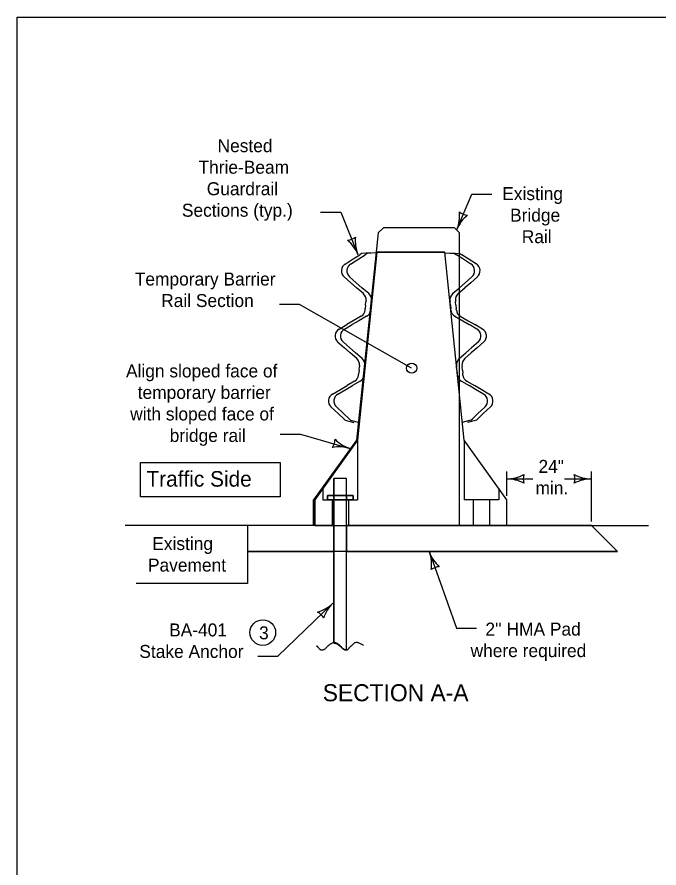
# Model space of a CAD drawing. Extents: x 10028 to 81668, y 3581 to 11018.
# Drawn here: x 13733 to 14485, y 8948 to 9944 of the extents above; entities that cross this region are included whole.
import ezdxf

# ---------------------------------------------------------------- set-up
doc = ezdxf.new("R2010")
doc.units = 0
for name, color, linetype in [('dsnCellsNorthArrow', 7, 'Continuous'), ('dsnTextTabulation', 7, 'Continuous'), ('Level 41', 7, 'Continuous'), ('Level 9', 7, 'Continuous'), ('SheetBorder', 7, 'Continuous')]:
    doc.layers.add(name, color=color, linetype=linetype)

msp = doc.modelspace()

# ---------------------------------------------------------------- linework, layer by layer
at = {"layer": 'dsnCellsNorthArrow'}
for p, q in [((14162.04, 9697.14), (14155.56, 9691.46)), ((14245.18, 9697.14), (14162.04, 9697.14)), ((14250.93, 9691.16), (14245.18, 9697.14)), ((14155.56, 9691.46), (14130.32, 9448.52)), ((14250.93, 9502.48), (14250.93, 9691.16)), ((14250.93, 9348.52), (14250.93, 9502.48)), ((14130.32, 9448.52), (14079.75, 9378.52)), ((14079.75, 9348.52), (14079.75, 9378.52))]:
    msp.add_line(p, q, dxfattribs=at)
at = {"layer": 'dsnTextTabulation'}
for p, q in [((14248.01, 9695.32), (14265.38, 9736.6)), ((14265.38, 9736.6), (14288.98, 9736.6)), ((14088.2, 9715.55), (14111.8, 9715.55)), ((14111.8, 9715.55), (14132.03, 9665.97)), ((14131.45, 9448.52), (14153.95, 9668.52)), ((14136.25, 9666.95), (14134.02, 9665.54)), ((14146.96, 9667.77), (14136.25, 9666.95)), ((14142.65, 9666.95), (14140.42, 9665.54)), ((14153.36, 9667.77), (14142.65, 9666.95)), ((14153.95, 9668.52), (14233.95, 9668.52)), ((14256.45, 9448.52), (14233.95, 9668.52)), ((14234.35, 9667.77), (14245.05, 9666.95)), ((14240.74, 9667.77), (14251.45, 9666.95)), ((14245.05, 9666.95), (14247.29, 9665.54)), ((14251.45, 9666.95), (14253.68, 9665.54)), ((14116.98, 9654.79), (14126.48, 9660.78)), ((14123.38, 9654.79), (14132.87, 9660.78)), ((14126.48, 9660.78), (14134.02, 9665.54)), ((14132.88, 9660.78), (14140.42, 9665.54)), ((14254.83, 9660.78), (14247.29, 9665.54)), ((14261.23, 9660.78), (14253.68, 9665.54)), ((14264.32, 9654.79), (14254.83, 9660.78)), ((14270.72, 9654.79), (14261.23, 9660.78)), ((14115.82, 9639.74), (14123.62, 9632.93)), ((14122.22, 9639.74), (14130.02, 9632.93)), ((14265.49, 9639.74), (14257.69, 9632.93)), ((14271.88, 9639.74), (14264.08, 9632.93)), ((14123.62, 9632.93), (14130.33, 9627.08)), ((14130.02, 9632.93), (14136.73, 9627.08)), ((14138.34, 9620.09), (14130.33, 9627.08)), ((14144.74, 9620.09), (14136.73, 9627.08)), ((14242.96, 9620.09), (14250.97, 9627.08)), ((14249.36, 9620.09), (14257.37, 9627.08)), ((14257.69, 9632.93), (14250.97, 9627.08)), ((14264.08, 9632.93), (14257.37, 9627.08)), ((14063.62, 9607.48), (14040.02, 9607.48)), ((14194.92, 9532.77), (14063.62, 9607.48)), ((14141, 9606.59), (14140.63, 9602.86)), ((14140.98, 9606.45), (14141.36, 9610.33)), ((14141.53, 9612.08), (14141.36, 9610.33)), ((14147.39, 9606.59), (14147.03, 9602.86)), ((14147.38, 9606.45), (14147.76, 9610.33)), ((14147.93, 9612.08), (14147.76, 9610.33)), ((14239.77, 9612.08), (14239.95, 9610.33)), ((14240.32, 9606.45), (14239.95, 9610.33)), ((14240.31, 9606.59), (14240.67, 9602.86)), ((14246.17, 9612.08), (14246.34, 9610.33)), ((14246.72, 9606.45), (14246.34, 9610.33)), ((14246.71, 9606.59), (14247.07, 9602.86)), ((14140.44, 9600.82), (14140.63, 9602.86)), ((14146.83, 9600.82), (14147.03, 9602.86)), ((14240.87, 9600.82), (14240.67, 9602.86)), ((14247.27, 9600.82), (14247.07, 9602.86)), ((14126.57, 9588.28), (14118.85, 9583.83)), ((14132.97, 9588.28), (14125.25, 9583.83)), ((14135.76, 9593.58), (14126.57, 9588.28)), ((14142.16, 9593.58), (14132.97, 9588.28)), ((14245.55, 9593.58), (14254.73, 9588.28)), ((14251.94, 9593.58), (14261.13, 9588.28)), ((14254.73, 9588.28), (14262.45, 9583.83)), ((14261.13, 9588.28), (14268.85, 9583.83)), ((14109.87, 9578.65), (14118.85, 9583.83)), ((14116.26, 9578.65), (14125.25, 9583.83)), ((14271.44, 9578.65), (14262.45, 9583.83)), ((14277.84, 9578.65), (14268.85, 9583.83)), ((14108.12, 9563.63), (14116.2, 9556.59)), ((14114.52, 9563.63), (14122.6, 9556.59)), ((14116.2, 9556.59), (14122.91, 9550.73)), ((14122.6, 9556.59), (14129.31, 9550.73)), ((14265.11, 9556.59), (14258.39, 9550.73)), ((14271.51, 9556.59), (14264.79, 9550.73)), ((14273.18, 9563.63), (14265.11, 9556.59)), ((14279.58, 9563.63), (14271.51, 9556.59)), ((14130.65, 9543.98), (14122.91, 9550.73)), ((14137.04, 9543.98), (14129.31, 9550.73)), ((14250.66, 9543.98), (14258.39, 9550.73)), ((14257.06, 9543.98), (14264.79, 9550.73)), ((14132.74, 9524.71), (14132.96, 9526.93)), ((14133.32, 9530.66), (14132.96, 9526.93)), ((14133.32, 9530.66), (14133.68, 9534.4)), ((14133.84, 9535.98), (14133.68, 9534.4)), ((14139.14, 9524.71), (14139.35, 9526.93)), ((14139.72, 9530.66), (14139.35, 9526.93)), ((14139.72, 9530.66), (14140.08, 9534.4)), ((14140.23, 9535.98), (14140.08, 9534.4)), ((14247.47, 9535.98), (14247.62, 9534.4)), ((14247.99, 9530.66), (14247.62, 9534.4)), ((14247.99, 9530.66), (14248.35, 9526.93)), ((14248.57, 9524.71), (14248.35, 9526.93)), ((14253.87, 9535.98), (14254.02, 9534.4)), ((14254.38, 9530.66), (14254.02, 9534.4)), ((14254.38, 9530.66), (14254.75, 9526.93)), ((14254.96, 9524.71), (14254.75, 9526.93)), ((14128.06, 9517.47), (14119.17, 9512.35)), ((14134.46, 9517.47), (14125.57, 9512.35)), ((14253.24, 9517.47), (14262.14, 9512.35)), ((14259.64, 9517.47), (14268.54, 9512.35)), ((14102.17, 9502.55), (14111.45, 9507.9)), ((14108.57, 9502.55), (14117.85, 9507.9)), ((14111.45, 9507.9), (14119.17, 9512.35)), ((14117.85, 9507.9), (14125.57, 9512.35)), ((14269.86, 9507.9), (14262.14, 9512.35)), ((14276.25, 9507.9), (14268.54, 9512.35)), ((14279.14, 9502.55), (14269.86, 9507.9)), ((14285.54, 9502.55), (14276.25, 9507.9)), ((14100.4, 9487.55), (14108.81, 9479.61)), ((14106.8, 9487.55), (14115.2, 9479.61)), ((14280.91, 9487.55), (14272.5, 9479.61)), ((14287.3, 9487.55), (14278.9, 9479.61)), ((14108.81, 9479.61), (14115.29, 9473.48)), ((14115.2, 9479.61), (14121.69, 9473.48)), ((14272.5, 9479.61), (14266.02, 9473.48)), ((14278.9, 9479.61), (14272.42, 9473.48)), ((14116.96, 9471.9), (14115.29, 9473.48)), ((14116.96, 9471.9), (14127.31, 9469.03)), ((14123.36, 9471.9), (14121.69, 9473.48)), ((14123.36, 9471.9), (14133.71, 9469.03)), ((14264.35, 9471.9), (14254, 9469.03)), ((14270.74, 9471.9), (14260.39, 9469.03)), ((14264.35, 9471.9), (14266.02, 9473.48)), ((14270.74, 9471.9), (14272.42, 9473.48)), ((14040.93, 9455.58), (14064.54, 9455.58)), ((14064.54, 9455.58), (14122.64, 9438.73)), ((14081.45, 9378.52), (14131.45, 9448.52)), ((14306.45, 9378.52), (14256.45, 9448.52)), ((14306.45, 9383.51), (14306.45, 9411.87)), ((14405.49, 9353.28), (14405.49, 9411.87)), ((14306.45, 9403.11), (14336.86, 9403.11)), ((14374.18, 9403.11), (14405.49, 9403.11)), ((14081.45, 9348.52), (14081.45, 9378.52)), ((14306.45, 9348.52), (14306.45, 9378.52)), ((14081.45, 9348.52), (14306.45, 9348.52)), ((14215.75, 9317.4), (14247.38, 9228.36)), ((14038.11, 9195.72), (14102.52, 9257.52)), ((14247.38, 9228.36), (14270.98, 9228.36)), ((14014.5, 9195.72), (14038.11, 9195.72))]:
    msp.add_line(p, q, dxfattribs=at)
msp.add_circle((14020.5, 9223.19), 15, dxfattribs=at)
for centre, radius, start, end in [((14208.65, 9711.35), 42.5, 337.83753, 5.91002), ((14287.37, 9679.28), 42.5, 129.76504, 157.83753), ((14261.46, 9728.32), 16.42, 230.10418, 265.57088), ((14118.57, 9698.97), 16.42, 274.46679, 309.93349), ((14171.38, 9682.03), 42.5, 174.12765, 202.20014), ((14092.68, 9649.92), 42.5, 22.20014, 50.27263), ((14088.71, 9449.63), 16.42, 324.45544, 359.92214), ((14135.64, 9479.19), 42.5, 224.1163, 252.18879), ((14109.64, 9398.27), 42.5, 72.18879, 100.26128), ((14306.45, 9445.61), 42.5, 270, 298.07249), ((14342.09, 9403.11), 16.42, 162.26665, 197.73335), ((14369.85, 9403.11), 16.42, 342.26665, 17.73335), ((14405.49, 9445.61), 42.5, 241.92751, 270), ((14306.45, 9360.61), 42.5, 61.92751, 90), ((14405.49, 9360.61), 42.5, 90, 118.07249), ((14255.63, 9332.08), 42.5, 200.20763, 228.28012), ((14175.86, 9302.72), 42.5, 352.13514, 20.20763), ((14228.05, 9283.96), 16.42, 92.47427, 127.94098), ((14073.1, 9288.19), 42.5, 285.73709, 313.80957), ((14131.95, 9226.85), 42.5, 133.80957, 161.88206), ((14076.81, 9232.85), 16.42, 26.07622, 61.54292)]:
    msp.add_arc(centre, radius, start, end, dxfattribs=at)
for centre, major_axis, start_param, end_param in [((14122.06, 9646.83), (9.43, -0.92), 2.229659, 4.096128), ((14128.46, 9646.83), (9.43, -0.92), 2.229659, 4.096128), ((14259.24, 9646.83), (-9.43, -0.92), 2.187057, 4.053527), ((14265.64, 9646.83), (-9.43, -0.92), 2.187057, 4.053527), ((14132.1, 9613), (9.43, -0.92), 0, 0.954538), ((14138.5, 9613), (9.43, -0.92), 0, 0.954538), ((14249.21, 9613), (-9.43, -0.92), 5.328647, 6.283185), ((14255.6, 9613), (-9.43, -0.92), 5.328647, 6.283185), ((14131, 9601.74), (-9.43, 0.92), 2.187055, 3.141593), ((14137.4, 9601.74), (-9.43, 0.92), 2.187055, 3.141593), ((14250.31, 9601.74), (9.43, 0.92), 3.141593, 4.096131), ((14256.7, 9601.74), (9.43, 0.92), 3.141593, 4.096131), ((14114.62, 9570.49), (-9.43, 0.92), 5.32865, 7.195119), ((14121.02, 9570.49), (-9.43, 0.92), 5.32865, 7.195119), ((14266.68, 9570.49), (9.43, 0.92), 5.371251, 7.237721), ((14273.08, 9570.49), (9.43, 0.92), 5.371251, 7.237721), ((14124.4, 9536.9), (9.43, -0.92), 0, 0.954538), ((14130.8, 9536.9), (9.43, -0.92), 0, 0.954538), ((14256.9, 9536.9), (-9.43, -0.92), 5.328647, 6.283185), ((14263.3, 9536.9), (-9.43, -0.92), 5.328647, 6.283185), ((14123.31, 9525.63), (-9.43, 0.92), 2.187055, 3.141593), ((14129.7, 9525.63), (-9.43, 0.92), 2.187055, 3.141593), ((14258, 9525.63), (9.43, 0.92), 3.141593, 4.096131), ((14264.4, 9525.63), (9.43, 0.92), 3.141593, 4.096131), ((14106.93, 9494.38), (-9.43, 0.92), 5.32865, 7.195119), ((14113.32, 9494.38), (-9.43, 0.92), 5.32865, 7.195119), ((14274.38, 9494.38), (9.43, 0.92), 5.371251, 7.237721), ((14280.78, 9494.38), (9.43, 0.92), 5.371251, 7.237721)]:
    msp.add_ellipse(centre, major_axis=major_axis, ratio=0.994906, start_param=start_param, end_param=end_param, dxfattribs=at)
at = {"layer": 'Level 41'}
for p, q in [((14131.45, 9448.52), (14131.45, 9378.52)), ((14256.45, 9448.52), (14256.45, 9378.52)), ((14090.98, 9391.86), (14090.98, 9378.52)), ((14296.92, 9391.86), (14296.92, 9378.52)), ((14090.98, 9378.52), (14131.45, 9378.52)), ((14101.62, 9378.52), (14101.62, 9348.52)), ((14120.82, 9378.52), (14120.82, 9348.52)), ((14296.92, 9378.52), (14256.45, 9378.52)), ((14267.09, 9378.52), (14267.09, 9348.52)), ((14286.29, 9378.52), (14286.29, 9348.52))]:
    msp.add_line(p, q, dxfattribs=at)
at = {"layer": 'Level 9'}
for p, q in [((14153.95, 9668.52), (14131.45, 9448.52)), ((14233.95, 9668.52), (14153.95, 9668.52)), ((14256.45, 9448.52), (14233.95, 9668.52)), ((14131.45, 9448.52), (14081.45, 9378.52)), ((14306.45, 9378.52), (14256.45, 9448.52)), ((14118.72, 9403.52), (14103.72, 9403.52)), ((14103.72, 9403.52), (14103.72, 9383.52)), ((14118.72, 9403.52), (14103.72, 9403.52)), ((14103.72, 9210.9), (14103.72, 9403.52)), ((14118.72, 9383.52), (14118.72, 9403.52)), ((14118.72, 9203.34), (14118.72, 9403.52)), ((14081.45, 9378.52), (14081.45, 9348.52)), ((14096.22, 9383.52), (14096.22, 9378.52)), ((14103.72, 9383.52), (14096.22, 9383.52)), ((14096.22, 9378.52), (14096.22, 9383.52)), ((14096.22, 9378.52), (14103.72, 9378.52)), ((14103.72, 9383.52), (14118.72, 9383.52)), ((14118.72, 9383.52), (14103.72, 9383.52)), ((14103.72, 9383.52), (14103.72, 9378.52)), ((14103.72, 9378.52), (14103.72, 9383.52)), ((14118.72, 9378.52), (14103.72, 9378.52)), ((14103.72, 9378.52), (14103.72, 9210.9)), ((14103.72, 9378.52), (14118.72, 9378.52)), ((14118.72, 9383.52), (14118.72, 9378.52)), ((14118.72, 9378.52), (14118.72, 9383.52)), ((14118.72, 9203.34), (14118.72, 9378.52)), ((14118.72, 9378.52), (14126.22, 9378.52)), ((14306.45, 9348.52), (14306.45, 9378.52)), ((14002.74, 9348.52), (13859.32, 9348.52)), ((14002.74, 9348.52), (14002.74, 9318.08)), ((14081.45, 9348.52), (14002.74, 9348.52)), ((14081.45, 9348.52), (14002.74, 9348.52)), ((14002.74, 9348.52), (14002.74, 9280.52)), ((14101.62, 9348.52), (14081.45, 9348.52)), ((14081.45, 9348.52), (14306.45, 9348.52)), ((14103.72, 9348.52), (14101.62, 9348.52)), ((14103.72, 9318.08), (14103.72, 9348.52)), ((14120.82, 9348.52), (14118.72, 9348.52)), ((14118.72, 9348.52), (14118.72, 9318.08)), ((14267.09, 9348.52), (14120.82, 9348.52)), ((14286.29, 9348.52), (14267.09, 9348.52)), ((14306.45, 9348.52), (14286.29, 9348.52)), ((14405.49, 9348.52), (14306.45, 9348.52)), ((14306.45, 9348.52), (14472.54, 9348.52)), ((14435.93, 9318.08), (14405.49, 9348.52)), ((14405.49, 9348.52), (14435.93, 9318.08)), ((14002.74, 9318.08), (14103.72, 9318.08)), ((14435.93, 9318.08), (14002.74, 9318.08)), ((14118.72, 9318.08), (14435.93, 9318.08)), ((14002.74, 9280.52), (13872.29, 9280.52))]:
    msp.add_line(p, q, dxfattribs=at)
msp.add_lwpolyline([(13877.34, 9422.22), (14041, 9422.22), (14041, 9382.22), (13877.34, 9382.22)], close=True, dxfattribs=at)
for points in [[(14096.22, 9383.52), (14126.22, 9383.52), (14126.22, 9378.52), (14096.22, 9378.52)], [(14126.22, 9378.52), (14126.22, 9383.52), (14118.72, 9383.52)]]:
    msp.add_lwpolyline(points, dxfattribs=at)
msp.add_circle((14194.92, 9532.77), 5.96, dxfattribs=at)
for points, degree in [([(14138.45, 9208.16), (14130.24, 9213.53), (14123.29, 9206.9), (14117.3, 9200.27), (14106.56, 9212.9), (14098.35, 9209.42), (14090.15, 9200.59), (14083.83, 9207.53), (14083.89, 9207.51)], 2), ([(14103.72, 9210.9), (14104.76, 9210.96), (14108.85, 9210.2), (14114.73, 9203.29), (14118.02, 9203.17), (14118.72, 9203.34)], 3)]:
    msp.add_open_spline(points, degree=degree, dxfattribs=at)
at = {"layer": 'SheetBorder'}
msp.add_lwpolyline([(13732.52, 9944.02), (16867.53, 9944.02), (16867.53, 7924.02), (13732.52, 7924.02)], close=True, dxfattribs=at)

# ---------------------------------------------------------------- texts
at = {"layer": 'dsnCellsNorthArrow'}
for s, height, p in [('Nested ', 15.2, (13967.5, 9785.75)), ('Thrie-Beam', 15.2, (13945.16, 9760.55)), ('Guardrail ', 15.2, (13954.84, 9735.35)), ('Existing', 15.2, (14301.07, 9729.6)), ('Sections (typ.)', 15.2, (13925.69, 9710.15)), ('Bridge', 15.2, (14310.24, 9704.4)), ('Rail', 15.2, (14323.94, 9679.2)), ('Temporary Barrier', 15.2, (13870.51, 9629.6)), ('Rail Section', 15.2, (13901.46, 9604.4)), ('Align sloped face of', 15.2, (13860.22, 9522.02)), ('temporary barrier', 15.2, (13873.97, 9496.82)), ('with sloped face of ', 15.2, (13865.13, 9471.62)), ('bridge rail', 15.2, (13911.39, 9446.42)), ('24"', 15.2, (14343.51, 9410.21)), ('Traffic Side', 18.24, (13884.19, 9394.07)), ('min.', 15.2, (14340.01, 9385.01)), ('Existing', 15.2, (13891.02, 9319.82)), ('Pavement', 15.2, (13885.96, 9294.62)), ('BA-401', 15.2, (13910.76, 9218.68)), ("2'' HMA Pad", 15.2, (14281.35, 9219.66)), ('Stake Anchor', 15.2, (13875.85, 9193.48)), ('where required', 15.2, (14263.97, 9194.46)), ('SECTION A-A', 20, (14090.71, 9142.74))]:
    msp.add_text(s, height=height, dxfattribs=at).set_placement(p)
at = {"layer": 'dsnTextTabulation'}
msp.add_text('3', height=15.2, dxfattribs=at).set_placement((14016.13, 9215.29))

doc.saveas('drawing.dxf')
